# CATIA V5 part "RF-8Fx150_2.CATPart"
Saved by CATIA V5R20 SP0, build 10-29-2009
Part number: _RF-8Fx150/2
Definition: NONE
Nomenclature: _RF-8Fx150/2
Source: Unknown
Description: PART-_RF-8Fx150/2-DESC
Bounding box of the stored display mesh (mm): x -150 to 18, y -4.5 to 4.5, z -4.5 to 4.5
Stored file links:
  C:\Users\Utente\Desktop\IO LAVORO\3D X SITO CF\X SITO\PLASTICA\RFF\RF-8Fx150_2.CATPart

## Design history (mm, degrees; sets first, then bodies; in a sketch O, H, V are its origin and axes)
Body1 "_RF-8Fx150/2" (main body)
  Solid1: solid without history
